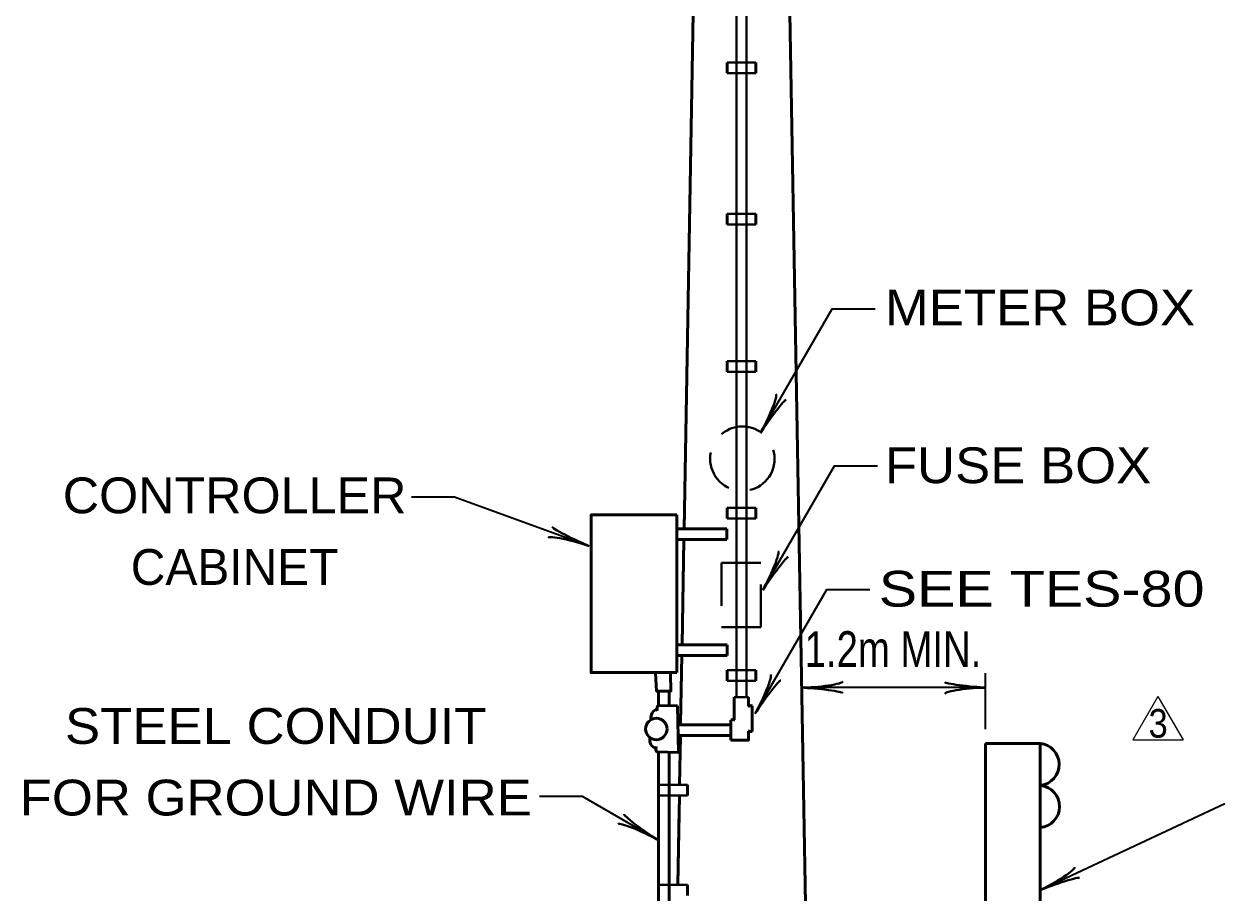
# Model space of a CAD drawing. Extents: x 14808 to 15663, y 10944 to 11488.
# Drawn here: x 14897.7 to 14998.3, y 11282.1 to 11354.9 of the extents above; entities that cross this region are included whole.
import ezdxf
from ezdxf.enums import TextEntityAlignment as Align

# ---------------------------------------------------------------- set-up
doc = ezdxf.new("R2010")
doc.units = 0
doc.header["$LTSCALE"] = 1.2
doc.linetypes.add('MEDIUM_DASHED', pattern=[4.5, 3, -1.5])
doc.layers.add('1', color=7, linetype='Continuous', lineweight=53)

msp = doc.modelspace()

# ---------------------------------------------------------------- linework, layer by layer
at = {"layer": '1'}
for p, q in [((14955.422, 11450.597), (14953.012, 11312.559)), ((14955.422, 11450.597), (14953.013, 11312.598)), ((14955.422, 11450.597), (14953.013, 11312.565)), ((14960.421, 11439.186), (14963.321, 11273.024)), ((14960.421, 11439.185), (14963.259, 11276.623)), ((14960.421, 11439.185), (14963.259, 11276.623)), ((14956.622, 11351.673), (14956.622, 11350.773)), ((14959.022, 11351.673), (14959.022, 11350.773)), ((14956.622, 11338.997), (14956.622, 11338.097)), ((14959.022, 11338.997), (14959.022, 11338.097)), ((14956.622, 11326.655), (14956.622, 11325.755)), ((14959.022, 11326.655), (14959.022, 11325.755)), ((14956.622, 11314.359), (14956.622, 11313.459)), ((14959.022, 11314.359), (14959.022, 11313.459)), ((14952.422, 11313.759), (14952.422, 11300.559)), ((14956.609, 11312.598), (14952.409, 11312.598)), ((14956.609, 11312.598), (14956.609, 11311.698)), ((14956.609, 11311.698), (14952.409, 11311.698)), ((14952.997, 11311.698), (14952.844, 11302.895)), ((14952.997, 11311.659), (14952.844, 11302.892)), ((14952.997, 11311.657), (14952.844, 11302.892)), ((14956.622, 11302.892), (14952.422, 11302.892)), ((14956.622, 11302.892), (14956.622, 11301.992)), ((14956.622, 11301.992), (14952.422, 11301.992)), ((14952.828, 11301.992), (14952.728, 11296.276)), ((14952.828, 11301.992), (14952.728, 11296.276)), ((14956.622, 11300.768), (14956.622, 11299.868)), ((14959.022, 11300.768), (14959.022, 11299.868)), ((14950.871, 11299), (14950.871, 11297.8)), ((14951.771, 11299), (14951.771, 11297.8)), ((14957.225, 11298.496), (14957.225, 11296.589)), ((14958.425, 11298.496), (14958.425, 11297.735)), ((14950.871, 11297.8), (14952.471, 11297.758)), ((14952.471, 11297.758), (14952.539, 11293.855)), ((14958.725, 11297.776), (14958.725, 11295.616)), ((14956.925, 11294.896), (14956.925, 11296.576)), ((14956.893, 11296.173), (14952.499, 11296.173)), ((14956.893, 11295.273), (14952.514, 11295.273)), ((14952.709, 11295.19), (14952.639, 11291.161)), ((14952.709, 11295.182), (14952.639, 11291.159)), ((14952.709, 11295.182), (14952.639, 11291.146)), ((14978.258, 11273.001), (14978.258, 11294.621)), ((14978.258, 11294.621), (14982.845, 11294.621)), ((14982.845, 11273.001), (14982.845, 11294.621)), ((14950.77, 11293.901), (14952.539, 11293.855)), ((14950.871, 11293.898), (14950.871, 11275.6)), ((14951.771, 11293.875), (14951.771, 11275.6)), ((14953.29, 11291.159), (14953.29, 11290.259)), ((14952.623, 11290.241), (14952.493, 11282.777)), ((14952.623, 11290.259), (14952.494, 11282.829)), ((14952.603, 11289.08), (14952.493, 11282.772)), ((14953.29, 11282.772), (14953.29, 11281.872))]:
    msp.add_line(p, q, dxfattribs=at)
at = {"layer": '1', "lineweight": 40}
for p, q in [((14957.402, 11401.697), (14957.402, 11298.497)), ((14958.242, 11401.697), (14958.242, 11298.497)), ((14956.622, 11351.673), (14959.022, 11351.673)), ((14956.622, 11350.773), (14959.022, 11350.773)), ((14956.622, 11338.997), (14959.022, 11338.997)), ((14956.622, 11338.097), (14959.022, 11338.097)), ((14956.622, 11326.655), (14959.022, 11326.655)), ((14956.622, 11325.755), (14959.022, 11325.755)), ((14956.622, 11314.359), (14959.022, 11314.359)), ((14956.622, 11313.459), (14959.022, 11313.459)), ((14956.622, 11300.768), (14959.022, 11300.768)), ((14956.622, 11299.868), (14959.022, 11299.868)), ((14958.425, 11298.496), (14957.225, 11298.496)), ((14950.89, 11291.159), (14953.29, 11291.159)), ((14950.89, 11290.259), (14953.29, 11290.259)), ((14950.89, 11282.772), (14953.29, 11282.772))]:
    msp.add_line(p, q, dxfattribs=at)
at = {"layer": '1', "lineweight": 35}
for p, q in [((14978.258, 11295.821), (14978.258, 11300.494)), ((14978.319, 11299.294), (14962.859, 11299.294)), ((14982.823, 11282.312), (14998.328, 11289.582))]:
    msp.add_line(p, q, dxfattribs=at)
at = {"layer": '1', "lineweight": 25}
for p, q in [((14992.712, 11298.556), (14990.612, 11294.918)), ((14992.712, 11298.556), (14994.812, 11294.918)), ((14990.612, 11294.918), (14994.812, 11294.918))]:
    msp.add_line(p, q, dxfattribs=at)
at = {"layer": '1', "lineweight": 35}
for points in [[(14959.426, 11320.637), (14965.426, 11331.03), (14969.026, 11331.03)], [(14959.617, 11307.481), (14965.617, 11317.874), (14969.217, 11317.874)], [(14945.057, 11311.154), (14933.78, 11315.258), (14930.18, 11315.258)], [(14958.979, 11297.135), (14964.979, 11307.528), (14968.579, 11307.528)], [(14950.74, 11286.567), (14944.505, 11290.167), (14940.905, 11290.167)]]:
    msp.add_lwpolyline(points, dxfattribs=at)
at = {"layer": '1'}
for points in [[(14952.422, 11313.759), (14945.222, 11313.759), (14945.222, 11300.559), (14952.422, 11300.559)], [(14951.882, 11300.5), (14951.908, 11299), (14950.708, 11299), (14950.63, 11300.498)], [(14958.425, 11295.656), (14958.425, 11294.896), (14956.925, 11294.896)]]:
    msp.add_lwpolyline(points, dxfattribs=at)
at = {"layer": '1', "linetype": 'MEDIUM_DASHED', "lineweight": 40}
msp.add_lwpolyline([(14956.148, 11309.745), (14956.148, 11304.345), (14959.448, 11304.345), (14959.448, 11309.745)], close=True, dxfattribs=at)
msp.add_circle((14957.899, 11318.474), 2.7, dxfattribs=at)
at = {"layer": '1'}
msp.add_circle((14950.693, 11295.831), 0.9, dxfattribs=at)
for centre, radius, start, end in [((14951.022, 11296.774), 0.783, 108.38078, 191.40608), ((14958.63, 11297.346), 0.44, 77.53484, 124.39267), ((14957.093, 11296.169), 0.44, 65.60733, 112.46516), ((14958.632, 11296.044), 0.44, 235.60733, 282.46516), ((14950.921, 11294.926), 0.783, 168.59392, 251.61922), ((14982.664, 11292.857), 1.774, 277.12572, 84.14888), ((14982.703, 11289.333), 1.774, 274.53924, 84.14888)]:
    msp.add_arc(centre, radius, start, end, dxfattribs=at)
at = {"layer": '1', "lineweight": 40}
for centre, major_axis, ratio, start_param, end_param in [((14959.793, 11321.937), (-0.909, -1.949), 0.122415, 0.8963533, 3.1415927), ((14960.318, 11321.675), (1.236, 1.72), 0.07063, 6.2823074, 8.5597026), ((14943.88, 11311.852), (-1.909, 0.919), 0.07063, 6.2823074, 8.5597026), ((14943.713, 11311.29), (2.078, -0.557), 0.122415, 0.8963533, 3.1415927), ((14959.985, 11308.781), (-0.909, -1.949), 0.122415, 0.8963533, 3.1415927), ((14960.51, 11308.519), (1.236, 1.72), 0.07063, 6.2823074, 8.5597026), ((14959.346, 11298.435), (-0.909, -1.949), 0.122415, 0.8963533, 3.1415927), ((14959.871, 11298.173), (1.236, 1.72), 0.07063, 6.2823074, 8.5597026), ((14964.204, 11299.04), (-2.108, 0.211), 0.07063, 3.1407148, 5.41811), ((14964.204, 11299.04), (-2.108, 0.211), 0.07063, 3.1407148, 5.41811), ((14964.169, 11299.626), (-2.143, -0.187), 0.122415, 0.8963533, 3.1415927), ((14964.169, 11299.626), (-2.143, -0.187), 0.122415, 0.8963533, 3.1415927), ((14977.009, 11298.962), (2.143, 0.187), 0.122415, 0.8963533, 3.1415927), ((14976.974, 11299.548), (2.108, -0.211), 0.07063, 3.1407148, 5.41811), ((14949.703, 11287.459), (1.72, -1.236), 0.07063, 3.1407148, 5.41811), ((14949.441, 11286.934), (1.949, -0.909), 0.122415, 0.8963533, 3.1415927), ((14983.868, 11283.168), (-1.861, -1.079), 0.122415, 0.8963533, 3.1415927), ((14984.149, 11282.653), (-1.998, -0.704), 0.07063, 3.1407148, 5.41811)]:
    msp.add_ellipse(centre, major_axis=major_axis, ratio=ratio, start_param=start_param, end_param=end_param, dxfattribs=at)
at = {"layer": '1'}
for centre, major_axis, start_param, end_param in [((14950.922, 11297.503), (-0.051, 0.296), 6.2829893, 8.3216807), ((14950.821, 11294.197), (-0.051, -0.296), 4.2446899, 6.2833813)]:
    msp.add_ellipse(centre, major_axis=major_axis, ratio=0.545945, start_param=start_param, end_param=end_param, dxfattribs=at)

# ---------------------------------------------------------------- texts
for s, height, width, p in [('METER BOX', 3, 1.1, (14969.836, 11329.643)), ('FUSE BOX', 3, 1.1, (14969.836, 11316.423)), ('SEE TES-80', 3, 1.2, (14969.325, 11306.077)), ('3', 2.4, 0.9, (14991.924, 11295.1))]:
    msp.add_text(s, height=height, dxfattribs=dict(at, width=width)).set_placement(p)
for s, width, p in [('CONTROLLER', 1.05, (14915.36, 11313.899)), ('1.2m MIN.', 0.8, (14970.515, 11301.019)), ('STEEL CONDUIT', 1.1, (14918.809, 11294.581)), ('FOR GROUND WIRE', 1.1, (14918.809, 11288.581))]:
    msp.add_text(s, height=3, dxfattribs=dict(at, width=width)).set_placement(p, align=Align.CENTER)
msp.add_text('CABINET', height=3, dxfattribs=at).set_placement((14915.36, 11307.899), align=Align.CENTER)

doc.saveas('drawing.dxf')
